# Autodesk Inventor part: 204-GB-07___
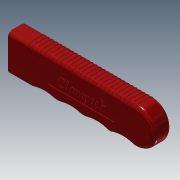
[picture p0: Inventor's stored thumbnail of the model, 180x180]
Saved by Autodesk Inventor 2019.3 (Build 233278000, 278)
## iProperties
Created: 2012-09
Part Number: 204-GB-07___
Material: Ogólny
Document SubType Name: Modeling
Designer: CADENGINEERING4
Density: 1 g/cm^3
Appearance: Czerwona
Author: CADENGINEERING4
Revision Number: ÈÎºÎ
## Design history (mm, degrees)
feature "NONE"
node "Bryła1"
